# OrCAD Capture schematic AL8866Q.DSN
size Custom; title: AL8866Q,100V High Power Buck-Boost LED Controller; rev: 1.0; note: DSXXXXX Rev. 1 - 2
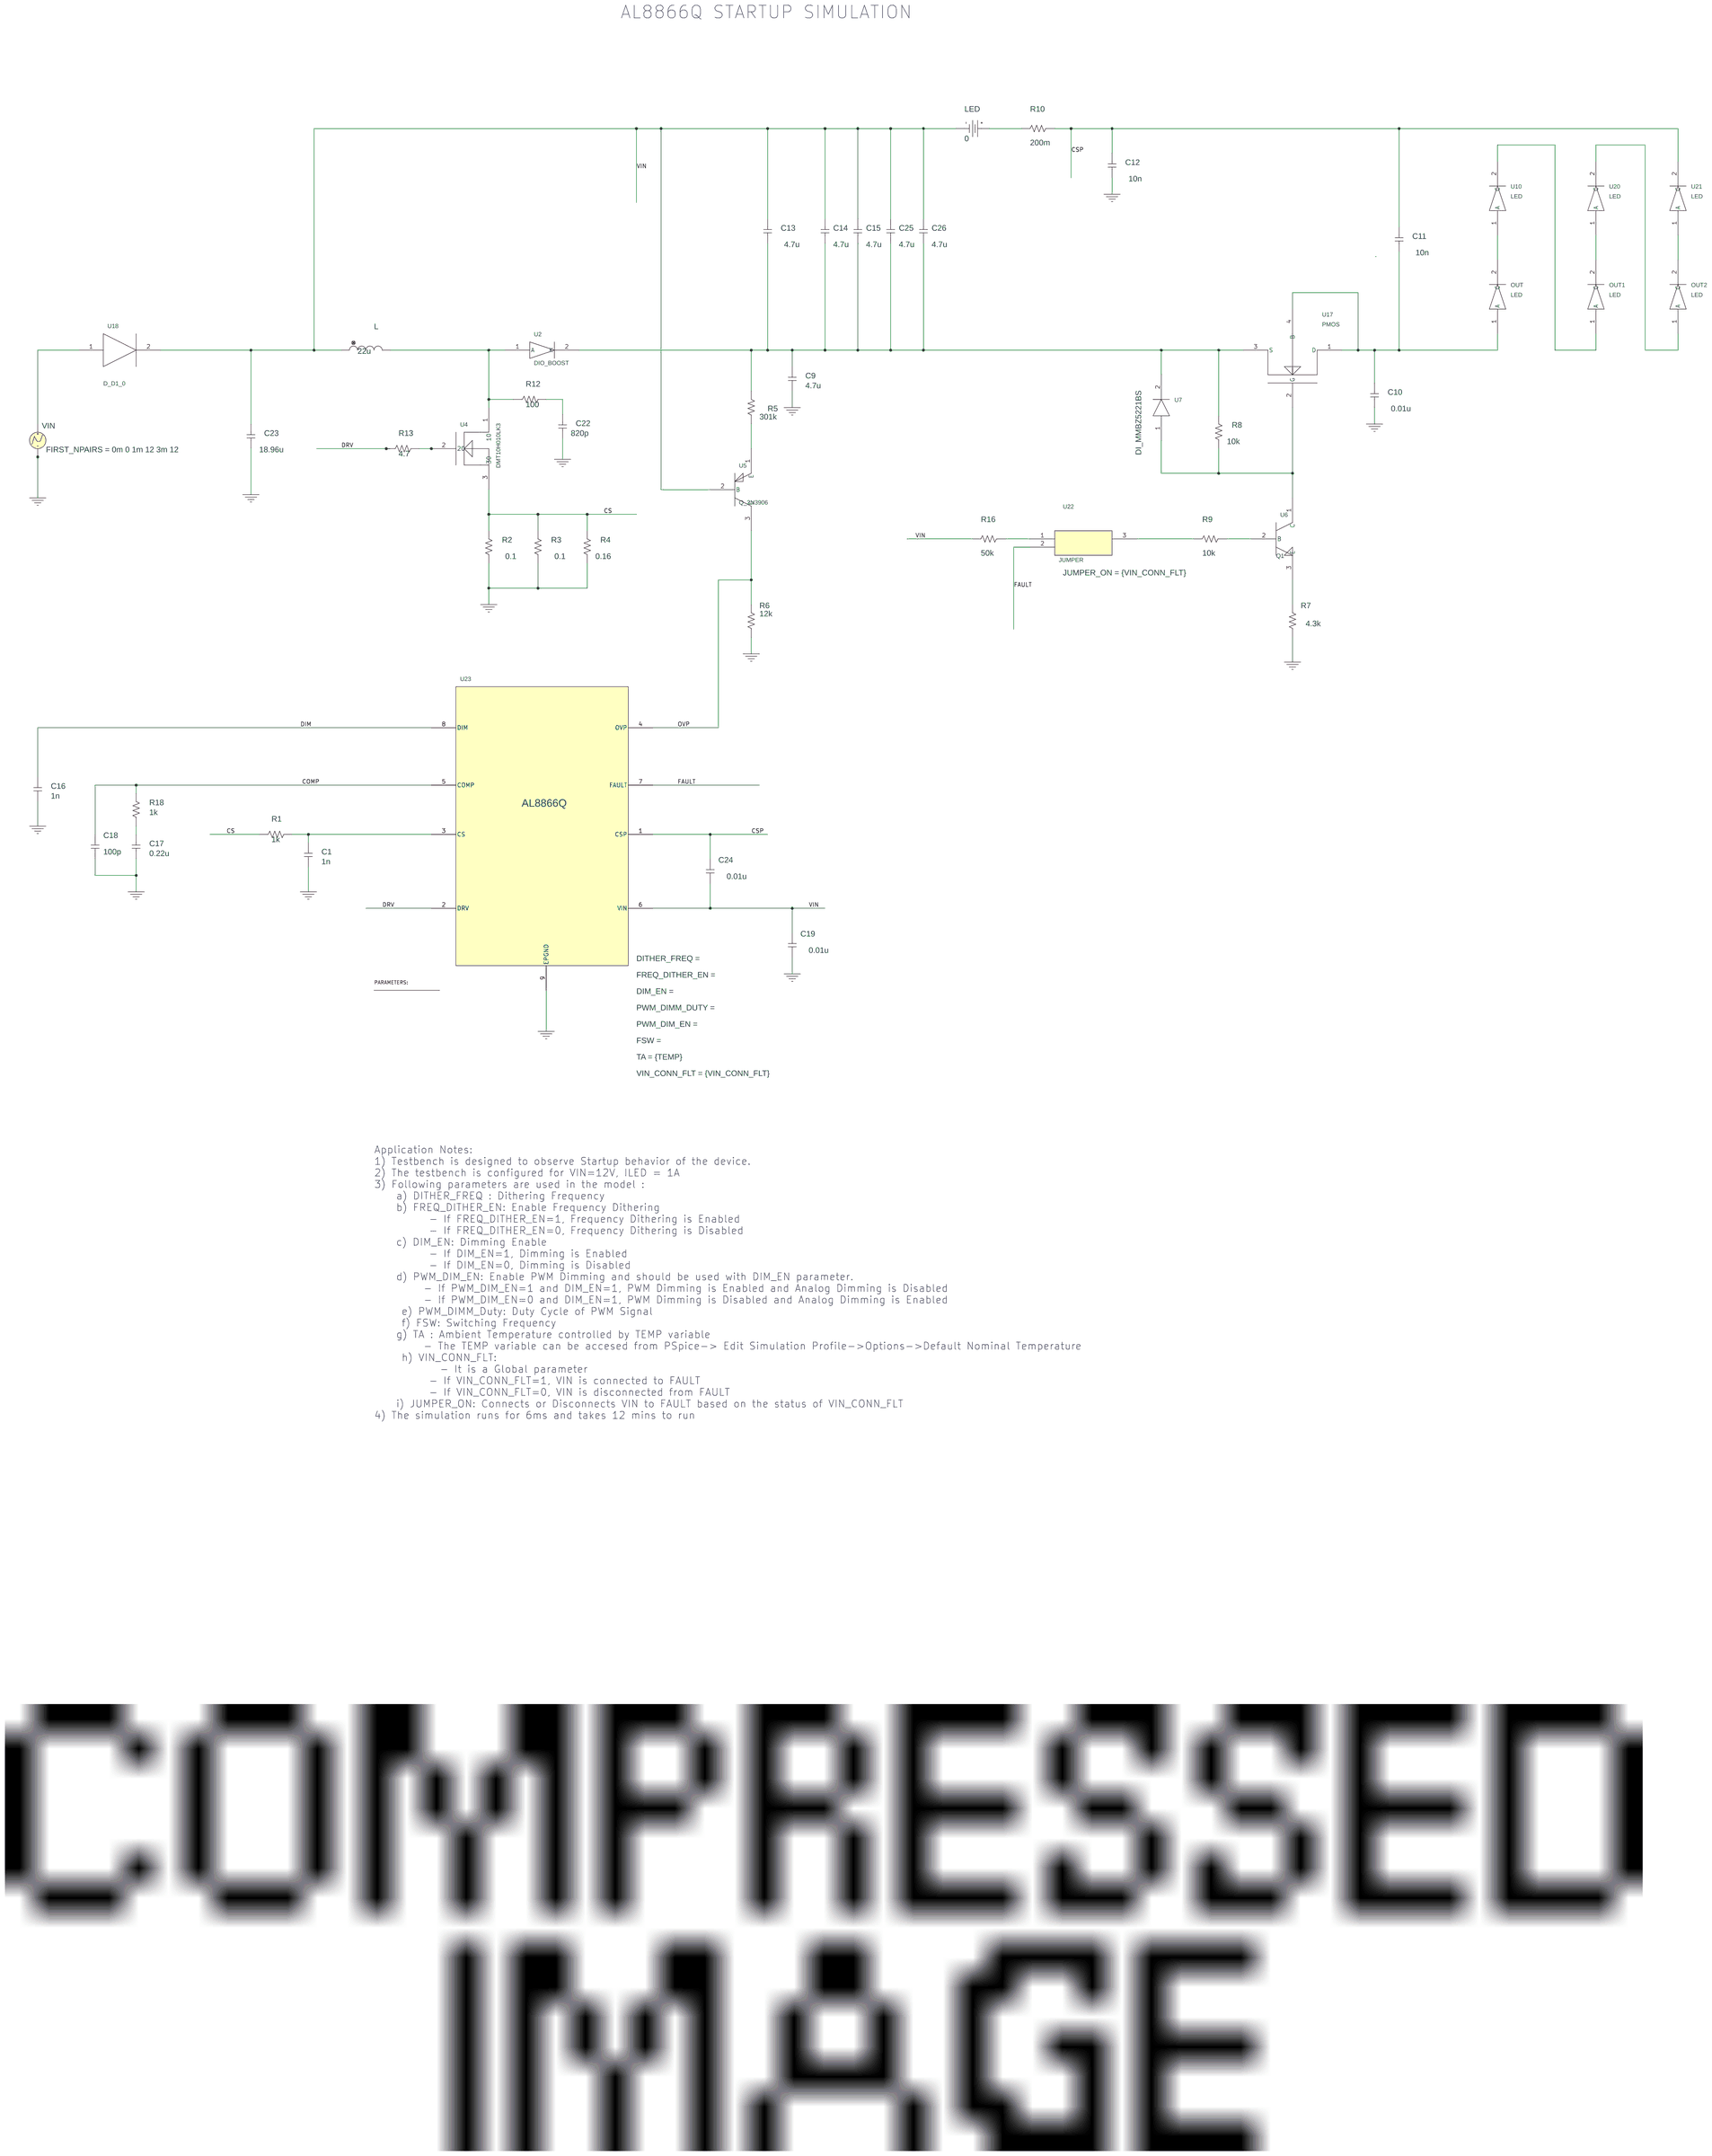
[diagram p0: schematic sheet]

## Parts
1  PARAM
C1  1n  [RAD/CK05]
C9  4.7u  [RAD/CK05]
C10  0.01u  [RAD/CK05]
C11  10n  [RAD/CK05]
C12  10n  [RAD/CK05]
C13  4.7u  [RAD/CK05]
C14  4.7u  [RAD/CK05]
C15  4.7u  [RAD/CK05]
C16  1n  [RAD/CK05]
C17  0.22u  [RAD/CK05]
C18  100p  [RAD/CK05]
C19  0.01u  [RAD/CK05]
C22  820p  [RAD/CK05]
C23  18.96u  [RAD/CK05]
C24  0.01u  [RAD/CK05]
C25  4.7u  [RAD/CK05]
C26  4.7u  [RAD/CK05]
L  22u  [DISC/.350x.175/LS.200x.100/.034]
LED  VDC
OUT  LED
OUT1  LED
OUT2  LED
R1  1k  [AX/RC05]
R2  0.1  [AX/RC05]
R3  0.1  [AX/RC05]
R4  0.16  [AX/RC05]
R5  301k  [AX/RC05]
R6  12k  [AX/RC05]
R7  4.3k  [AX/RC05]
R8  10k  [AX/RC05]
R9  10k  [AX/RC05]
R10  200m  [AX/RC05]
R12  100  [AX/RC05]
R13  4.7  [AX/RC05]
R16  50k  [AX/RC05]
R18  1k  [AX/RC05]
U2  DIO_BOOST
U4  DMT10H010LK3
U5  Q_2N3906
U6  Q1
U7  DI_MMBZ5221BS
U10  LED
U17  PMOS
U18  D_D1_0
U20  LED
U21  LED
U22  JUMPER
U23  AL8866Q
VIN  VPWL_GENERIC

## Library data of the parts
1 = PARAM: VIN_CONN_FLT: 0
C1 C9-C19 C22-C26 = C
L = L
LED = VDC: DC: 0
OUT OUT1 OUT2 U10 U20 U21 = LED_0
R1-R10 R12 R13 R16 R18 = R
U2 = DIO_BOOST_0
U4 = DMT10H010LK3_1
U5 = Q_1
U6 = Q1_0
U7 = DI_MMBZ5221BS_0
U17 = PMOS_0
U18 = D_D1_0
U22 = JUMPER_1: JUMPER_ON: {VIN_CONN_FLT}
U23 = AL8866Q_3: TA: {TEMP}; VIN_CONN_FLT: {VIN_CONN_FLT}
VIN = VPWL_GENERIC: AppProp: No_reps$POINTS_TYPE_PWL$0$0; FIRST_NPAIRS: 0m 0 1m 12 3m 12; PSpiceTemplate: V^@REFDES %+ %- ?DC|DC @DC| ?AC|AC @AC| PWL ?TSF|TIME_SCALE_FACTOR=@TSF| ?VSF|VALUE_SCALE_FACTOR=@VSF| ?REPEAT_VALUE| \n+ REPEAT FOR @REPEAT_VALUE| \n+ @FIRST_NPAIRS ?SECOND_NPAIRS|\n+ @SECOND_NPAIRS ?THIRD_NPAIRS/\n+ @THIRD_NPAIRS/| ?REPEAT_VALUE| \n+ ENDREPEAT|

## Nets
VIN: C13.2 C14.2 C15.2 C19.2 C23.2 C24.1 C25.2 C26.2 L.1 LED.1(-) R16.2 U5.2(B) U18.2 U23.6(VIN)
0: C1.1 C9.1 C10.1 C12.1 C16.1 C17.1 C18.1 C19.1 C22.1 C23.1 R2.1 R3.1 R4.1 R6.1 R7.1 U23.9(EPGND) VIN.2(-)
COMP: C18.2 R18.2 U23.5(COMP)
CS: R1.1 R2.2 R3.2 R4.2 U4.3(30)
CSP: C11.2 C12.2 C24.2 R10.1 U21.2(C) U23.1(CSP)
DIM: C16.2 U23.8(DIM)
DRV: R13.1 U23.2(DRV)
FAULT: U22.2 U23.7(FAULT)
OVP: R6.2 U5.3(C) U23.4(OVP)
N225579: R9.1 U6.2(B)
N225621: C1.2 R1.2 U23.3(CS)
N225803: L.2 R12.1 U2.1(A) U4.1(10)
N226005: C10.2 C11.1 OUT.1(A) U17.1(D) U17.4(B)
N226099: R16.1 U22.1
N226105: C9.2 C13.1 C14.1 C15.1 C25.1 C26.1 R5.2 R8.2 U2.2(K) U7.2 U17.3(S)
N226115: R9.2 U22.3
N226183: R5.1 U5.1(E)
N226249: R7.2 U6.3(E)
N226439: OUT.2(C) U10.1(A)
N226557: C17.2 R18.1
N226729: U18.1 VIN.1(+)
N226779: R8.1 U6.1(C) U7.1 U17.2(G)
N227087: C22.2 R12.2
N227201: R13.2 U4.2(20)
N227339: OUT1.2(C) U20.1(A)
N227389: OUT2.2(C) U21.1(A)
N227395: OUT1.1(A) U10.2(C)
N227417: OUT2.1(A) U20.2(C)
N232642: LED.0(+) R10.2

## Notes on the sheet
- AL8866Q STARTUP SIMULATION
- Application Notes:
  1) Testbench is designed to observe Startup behavior of the device.
  2) The testbench is configured for VIN=12V, ILED = 1A
  3) Following parameters are used in the model :
      a) DITHER_FREQ : Dithering Frequency
      b) FREQ_DITHER_EN: Enable Frequency Dithering
            - If FREQ_DITHER_EN=1, Frequency Dithering is Enabled
            - If FREQ_DITHER_EN=0, Frequency Dithering is Disabled
      c) DIM_EN: Dimming Enable
            - If DIM_EN=1, Dimming is Enabled
            - If DIM_EN=0, Dimming is Disabled
      d) PWM_DIM_EN: Enable PWM Dimming and should be used with DIM_EN parameter.
           - If PWM_DIM_EN=1 and DIM_EN=1, PWM Dimming is Enabled and Analog Dimming is Disabled
           - If PWM_DIM_EN=0 and DIM_EN=1, PWM Dimming is Disabled and Analog Dimming is Enabled
       e) PWM_DIMM_Duty: Duty Cycle of PWM Signal
       f) FSW: Switching Frequency
      g) TA : Ambient Temperature controlled by TEMP variable
           - The TEMP variable can be accesed from PSpice-> Edit Simulation Profile->Options->Default Nominal Temperature
       h) VIN_CONN_FLT:
              - It is a Global parameter
            - If VIN_CONN_FLT=1, VIN is connected to FAULT
            - If VIN_CONN_FLT=0, VIN is disconnected from FAULT
      i) JUMPER_ON: Connects or Disconnects VIN to FAULT based on the status of VIN_CONN_FLT
  4) The simulation runs for 6ms and takes 12 mins to run
